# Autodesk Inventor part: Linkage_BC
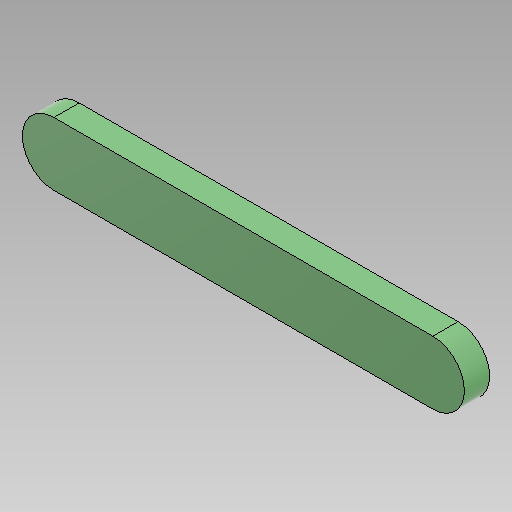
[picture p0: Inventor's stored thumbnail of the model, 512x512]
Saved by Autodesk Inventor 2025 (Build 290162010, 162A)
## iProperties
Created: 2024-10
Part Number: Linkage_BC
Material: Generic
Document SubType Name: Modeling
Designer: Dennis
Density: 1 g/cm^3
Appearance: Smooth - Dark Forest Green
Mass: 0.33927 g
Surface Area: 4.90686 cm^2
Volume: 0.33927 cm^3
Author: Dennis
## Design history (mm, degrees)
sketch "Sketch1"
  geometry: L1 (0, 0)-(30, 0); L2 (0, -2.5)-(30, -2.5); L3 (30, 2.5)-(0, 2.5); A1 r 2.5 centre (0, 0) between (0, 2.5) and (0, -2.5); A2 r 2.5 centre (30, 0) between (30, -2.5) and (30, 2.5); 1 further point
  constraints: 8 end point, 4 point on circle, 4 tangent, 2 centre point, 1 horizontal, 1 midpoint, 1 parallel
  dimensions: "d0" = 5 distance between parallel lines of L2 L3 (= w_); "d1" = 30 distance of L1.start L1.end (= BC_)
extrude "Extrusion1" new body sketch "Sketch1" stored distance "d2" = 2 (= t_); taper "d3" = 0 deg
body "Solid1"
other parameters: "BC_" = 30 [user parameter; used in 1 equation term], "w_" = 5 [user parameter; used in 1 equation term], "t_" = 2 [user parameter; used in 1 equation term]
